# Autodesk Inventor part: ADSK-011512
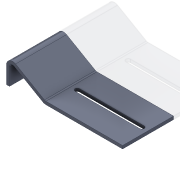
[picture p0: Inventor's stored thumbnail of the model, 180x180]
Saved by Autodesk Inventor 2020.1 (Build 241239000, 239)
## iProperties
Created: 2000-02
Part Number: ADSK-011512
Material: Pearson Stainless Steel
Document SubType Name: Modeling
Designer: sspink
Density: 8.03 g/cm^3
Sheet Metal Rule: Standard
Appearance: Pearson-Stainless
Mass: 157.103 g
Surface Area: 145.852 cm^2
Volume: 19.5646 cm^3
Control State: 0
Checked Out: False
Master: False
Shininess: 57.0
Length Units: 11269
Angle Units: 11279
Time Units: 11290
Mass Units: 11283
Length Display Precision: 3
Angle Display Precision: 2
Compacted: True
Cutlength: 2.00 X 5.36  (11 SI)
Material Desc: SHEET,S/S,11GA
Material_Number: A08458715
Dimensions: 114x22,8x50 mm
Mass: 0,157 kg
Density: 0.0
Volumn: 0.0
Area: 0.0
PropertySet Name: Model Information
Author: sspink
Revision Number: -
Title: ADSK-011512
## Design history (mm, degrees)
sketch "Sketch3"
  geometry: L1 (0, 50)-(0, 0) reference; L2 (-69.5, 27.25)-(-6, 27.25); L3 (-6, 27.25)-(-6, 22.75); L4 (-6, 22.75)-(-69.5, 22.75); L5 (-69.5, 22.75)-(-69.5, 27.25); A1 r 2.25 centre (-69.5, 25) between (-69.5, 27.25) and (-69.5, 22.75); A2 r 2.25 centre (-6, 25) between (-6, 22.75) and (-6, 27.25); 2 further points
  constraints: 8 end point, 4 point on circle, 2 centre point, 2 midpoint, 2 parallel, 2 tangent, 1 horizontal, 1 horizontal alignment, 1 perpendicular
  dimensions: "d28" = 4.5 distance of L2.end L3.end; "d29" = 63.5 distance of L3.end L4.end; "d30" = 6 distance between parallel lines of L3 L1
node "Extrusion3" dims "d32" = 25.4, "d33" = 0
fillet "Rundung3" dims "d46" = 6, "d47" = 3
node "Solide1"
  node "Extrusion1" dims "d4" = 50, "d5" = 0
sketch "Sketch1"
  geometry: L1 (114, 2.257)-(114, 5.257); L2 (0, 27.196)-(0, 0); L3 (0, 0)-(3, 0); L4 (3, 0)-(3, 22); L5 (114, 5.257)-(38, 5.257); L6 (38, 2.257)-(114, 2.257); L7 (38, 5.257)-(0, 27.196); L8 (3, 22)-(37.196, 2.257); L9 (38, 2.257)-(37.196, 2.257); 1 further point
  constraints: 18 end point, 3 perpendicular, 2 parallel, 1 coincident, 1 collinear, 1 horizontal
  dimensions: "d14" = 3 distance between parallel lines of L5 L6 (= thickness); "d17" = 114 distance between parallel lines of L1 L2; "d19" = 76 distance of L1.end L5.end; "d20" = 76 distance of L6.start L1.start; "d22" = 3 distance between parallel lines of L4 L2 (= thickness); "d23" = 3 distance between parallel lines of L7 L8 (= thickness); "d24" = 22 distance of L3.end L4.end; "d25" = 150 deg angle of L5 L7
node "Corps solides"
node "Corps surfaciques"
other parameters: "thickness" = 3 [user parameter; used in 4 equation terms], "d0" = 3 (= thickness), "Thickness" = 3.175, "BendRadius" = 3.175 (= Thickness), "BendReliefWidth" = 3.175 (= Thickness), "BendReliefDepth" = 1.5875 (= 0.5 x Thickness), "CornerReliefSize" = 7.14375 (= 2.25 x Thickness), "SeamGap" = 0.00508, "MinimumRemnant" = 6.35 (= 2 x Thickness), "TransitionRadius" = 3.175 (= BendRadius), "TailleRayonJacobi" = 3.175 (= Thickness), "TailleJeu" = 3.175 (= Thickness), "d44" = 3.175 (= Thickness)
